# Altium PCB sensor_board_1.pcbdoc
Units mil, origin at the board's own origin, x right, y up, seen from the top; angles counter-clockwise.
Board outline 4127.56 x 3017.72 mil, 2 copper layers (Top Layer, Bottom Layer); 44 components, 32 nets, 169 pads, 48 vias.
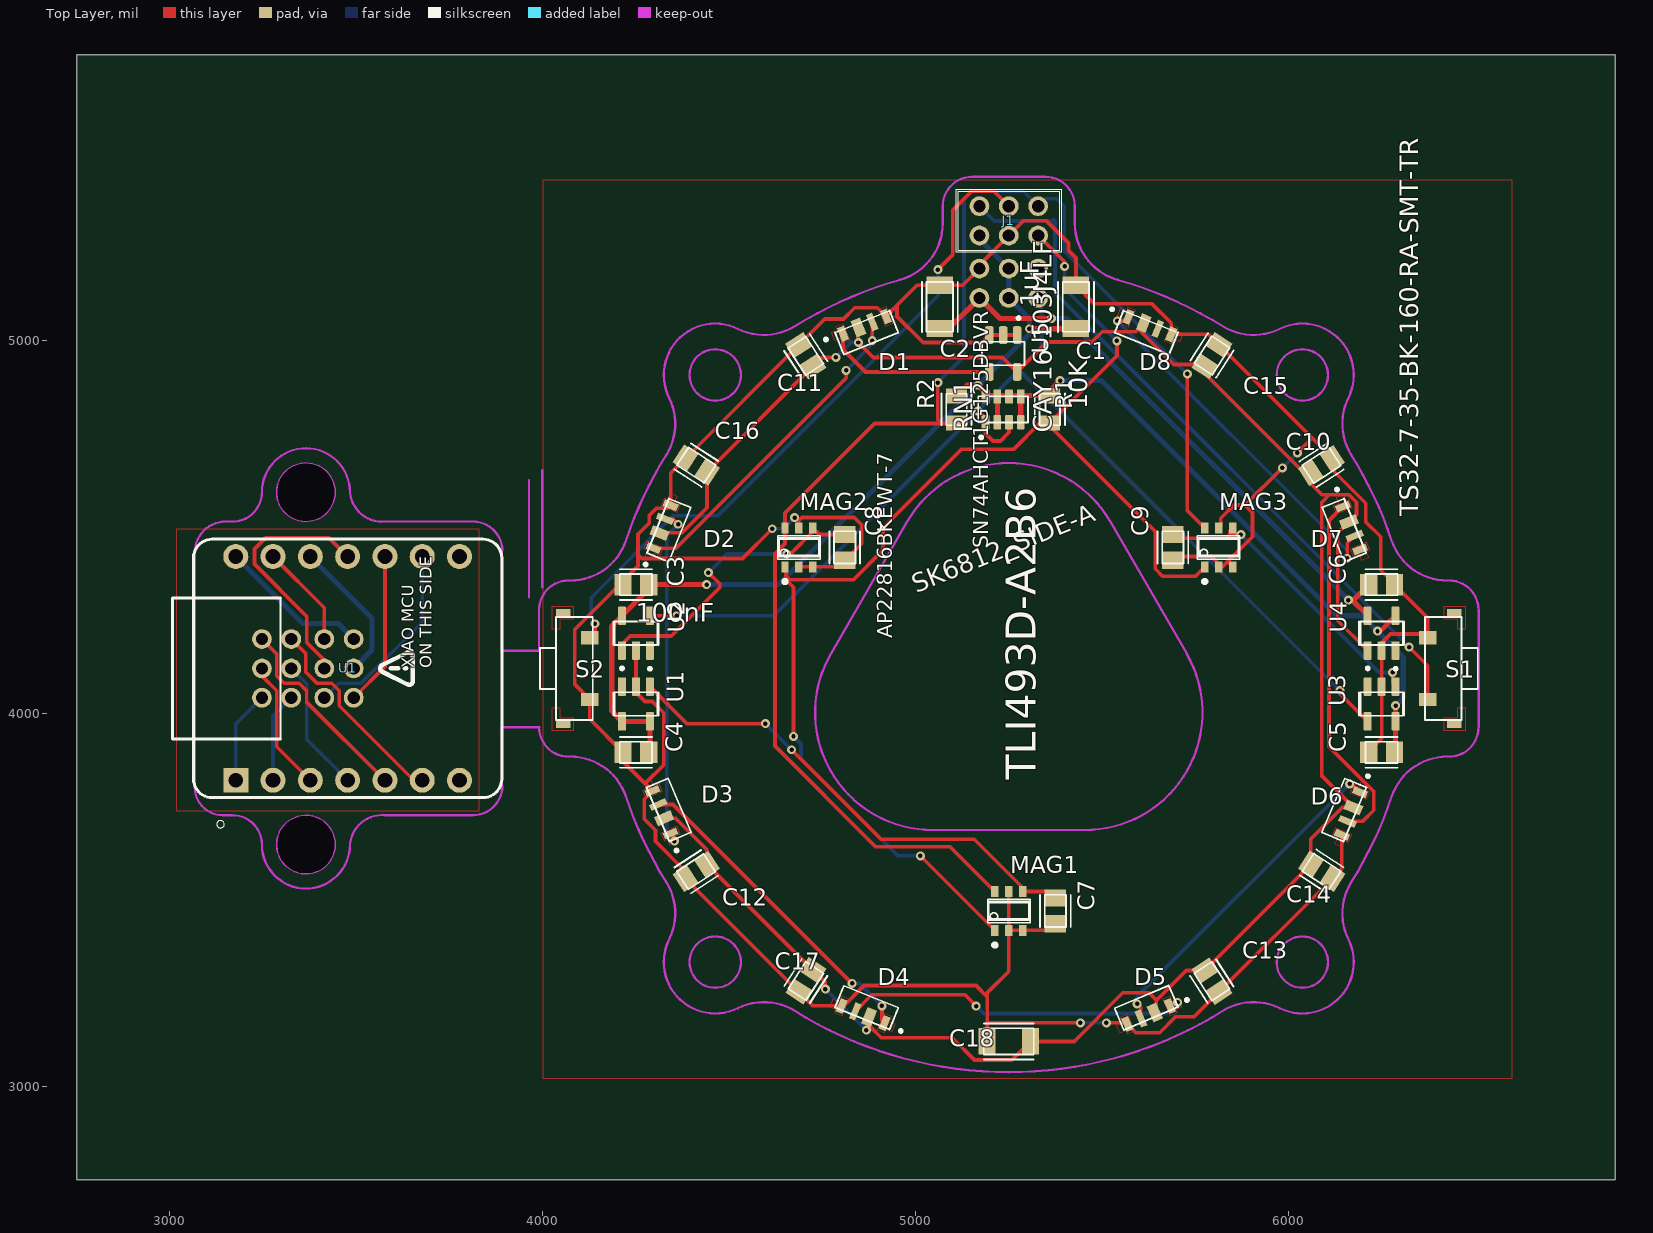
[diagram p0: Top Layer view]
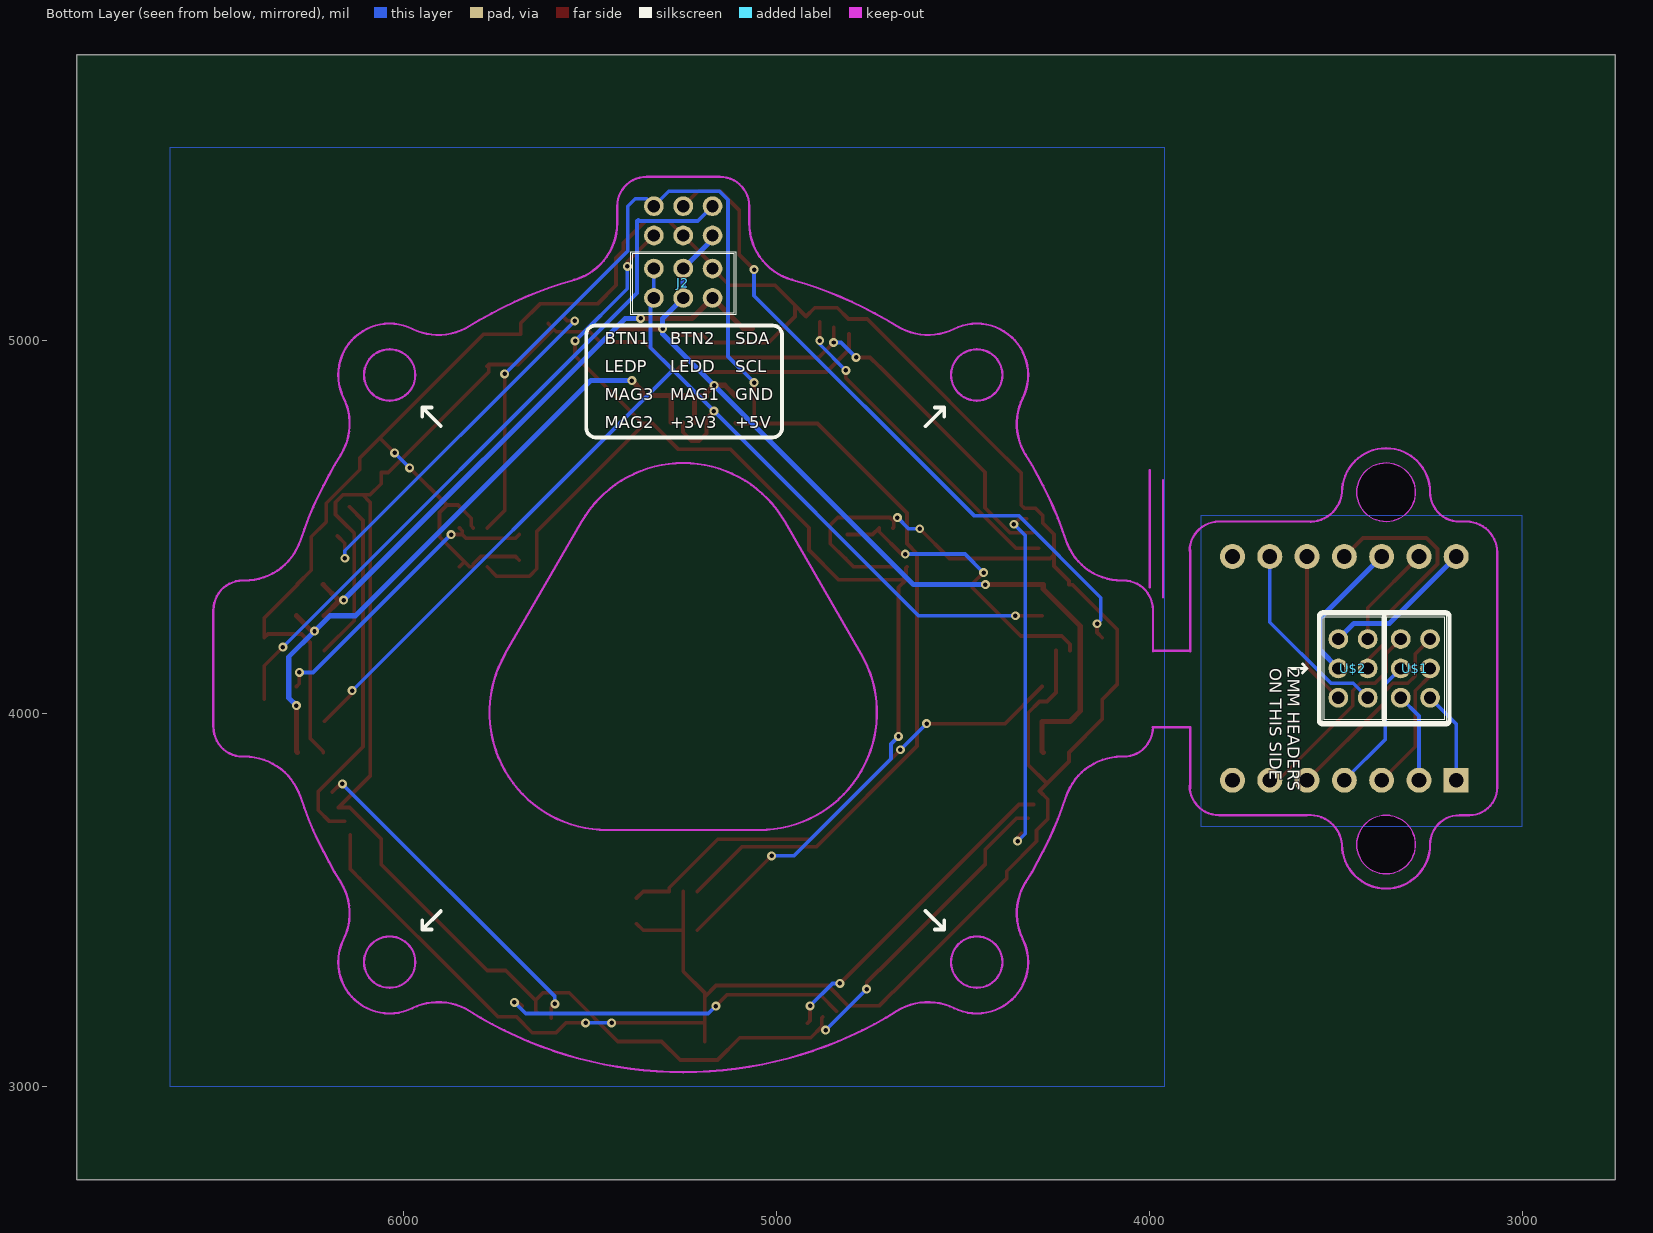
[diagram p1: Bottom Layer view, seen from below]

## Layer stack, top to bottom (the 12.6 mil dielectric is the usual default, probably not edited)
Top Layer: signal copper (thickness not stored)
Dielectric: dielectric 12.6, FR-4, Dk 4.8
Bottom Layer: signal copper (thickness not stored)

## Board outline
6877.56,2750 2750,2750 2750,5767.72 6877.56,5767.72
cut-out: 3444.05,3648.82 cw(c3365.31,3648.82) 3286.57,3648.82 cw(c3365.31,3648.82)
cut-out: 3444.05,4593.7 cw(c3365.31,4593.7) 3286.57,4593.7 cw(c3365.31,4593.7)

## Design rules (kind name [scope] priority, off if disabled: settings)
BoardOutlineClearance copperThickness1oz [All] p0: genericclearance=10 ignorepadtopadclearanceinfootprint=FALSE except(0: Arc-SplitContinuation Track-SplitContinuation SMDPad-SplitContinuation THPad-SplitContinuation Via-SplitContinuation Fill-SplitContinuation Poly-SplitContinuation Region-SplitContinuation Text-SplitContinuation; 6: SMDPad-CutoutEdge THPad-CutoutEdge Via-CutoutEdge Fill-CutoutEdge Region-CutoutEdge; 11.8: Track-OutlineEdge SMDPad-OutlineEdge THPad-OutlineEdge Via-OutlineEdge Fill-OutlineEdge Region-OutlineEdge Poly-OutlineEdge Text-OutlineEdge Track-CutoutEdge)
BoardOutlineClearance copperThickness2oz [All] p0: genericclearance=10 ignorepadtopadclearanceinfootprint=FALSE except(0: Arc-SplitContinuation Track-SplitContinuation SMDPad-SplitContinuation THPad-SplitContinuation Via-SplitContinuation Fill-SplitContinuation Poly-SplitContinuation Region-SplitContinuation Text-SplitContinuation; 6: SMDPad-CutoutEdge THPad-CutoutEdge Via-CutoutEdge Fill-CutoutEdge Region-CutoutEdge; 11.8: Track-OutlineEdge SMDPad-OutlineEdge THPad-OutlineEdge Via-OutlineEdge Fill-OutlineEdge Region-OutlineEdge Poly-OutlineEdge Text-OutlineEdge Track-CutoutEdge)
Clearance copperThickness1oz [(InNet('GND') OR InNet('N$1') OR InNet('N$2') OR InNet('N$4') OR InNet('N$5') OR InNet('N$6') OR InNet('G_5V') OR InNet('SCL') OR InNet('SDA') OR InNet('G_MAG1') OR InNet('G_MAG2') OR InNet('G_MAG3') OR InNet('BTN_1') OR InNet('BTN_2') OR InNet('LED_DIN') OR InNet('N$3') OR InNet('N$7') OR InNet('~EN_MAG2~') OR InNet('D3') OR InNet('D0') OR InNet('D1') OR InNet('D8') OR InNet('D9') OR InNet('D2') OR InNet('D10') OR InNet('SDA1') OR InNet('SCL1') OR InNet('GND1'))] p1: gap=7 ignorepadtopadclearanceinfootprint=FALSE except(4: Track-Track; 6: Track-SMDPad SMDPad-SMDPad Track-THPad SMDPad-THPad THPad-THPad Track-Via SMDPad-Via THPad-Via Via-Via Track-Fill SMDPad-Fill THPad-Fill Via-Fill Fill-Fill SMDPad-Region THPad-Region Via-Region Fill-Region Region-Region Track-Poly SMDPad-Poly THPad-Poly Via-Poly Fill-Poly Poly-Poly Track-Text SMDPad-Text THPad-Text Via-Text Fill-Text Region-Text Poly-Text Text-Text; 6.9: Track-Hole SMDPad-Hole THPad-Hole Via-Hole Fill-Hole Region-Hole Poly-Hole Text-Hole Sheet-Hole; 11.8: Track-Region Region-Poly Track-Sheet SMDPad-Sheet THPad-Sheet Via-Sheet Fill-Sheet Region-Sheet Poly-Sheet Text-Sheet)
Clearance copperThickness2oz [(InNet('5V') OR InNet('3V3') OR InNet('3V31') OR InNet('5V1'))] p1: gap=7 ignorepadtopadclearanceinfootprint=FALSE except(6: Track-SMDPad SMDPad-SMDPad Track-THPad SMDPad-THPad THPad-THPad Track-Via SMDPad-Via THPad-Via Via-Via Track-Fill SMDPad-Fill THPad-Fill Via-Fill Fill-Fill SMDPad-Region THPad-Region Via-Region Fill-Region Region-Region Track-Poly SMDPad-Poly THPad-Poly Via-Poly Fill-Poly Poly-Poly Track-Text SMDPad-Text THPad-Text Via-Text Fill-Text Region-Text Poly-Text Text-Text; 6.9: Track-Hole SMDPad-Hole THPad-Hole Via-Hole Fill-Hole Region-Hole Poly-Hole Text-Hole Sheet-Hole; 8: Track-Track; 11.8: Track-Region Region-Poly Track-Sheet SMDPad-Sheet THPad-Sheet Via-Sheet Fill-Sheet Region-Sheet Poly-Sheet Text-Sheet)
DiffPairsRouting differentialPair [All] p1: maxuncoupledlength=10 minlimit=5.9843 maxlimit=5.9843 mostfreqgap=5.9843 toplayer_minwidth=5 toplayer_prefwidth=10 toplayer_maxwidth=100 bottomlayer_minwidth=5 bottomlayer_prefwidth=10 bottomlayer_maxwidth=100
PasteMaskExpansion pasteMaskExpansion [All] p1: expansion=0
PlaneConnect innerPlane [All] p1: planeconnectstyle=Relief reliefexpansion=20 reliefentries=4 reliefconductorwidth=10 reliefairgap=10
PolygonConnect copperRegion [All] p1: connectstyle=Relief reliefentries=4 reliefconductorwidth=10 polygonreliefangle="90 Angle" airgapwidth=10
RoutingVias viaSize [All] p1: viastyle="Through Hole" holewidth=12.0078 minholewidth=11.811 maxholewidth=248.0314 width=24.0158 minwidth=19.685 maxwidth=393.7008
SolderMaskExpansion solderMaskExpansion [All] p1: useseparateexpansions=TRUE expansion=2.0079 expansionbottom=2.0079
Width copperThickness1oz [All] p1: maxlimit=100 minlimit=8 preferedwidth=10
Width copperThickness2oz [All] p1: maxlimit=100 minlimit=12 preferedwidth=14

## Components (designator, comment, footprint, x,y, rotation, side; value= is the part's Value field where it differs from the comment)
C1 "1uF" CAPC3216X135 5430.39,5090.87 r270 top
C2 "1uF" CAPC3216X135 5065.39,5090.87 r270 top
C3 "100nF" CAPC2012X110 4250.39,4345.87 r0 top
C4 "100nF" CAPC2012X110 4250.39,3895.87 r0 top
C5 "100nF" CAPC2012X110 6250.39,3895.87 r0 top
C6 "100nF" CAPC2012X110 6250.39,4345.87 r180 top
C7 "100nF" CAPC2012X110 5375.39,3470.87 r90 top
C8 "100nF" CAPC2012X110 4810.39,4445.87 r90 top
C9 "100nF" CAPC2012X110 5690.39,4445.87 r90 top
C10 "100nF" CAPC2012X110 6089.06,4665.51 r213 top
C11 "100nF" CAPC2012X110 4705.75,4959.54 r303 top
C12 "100nF" CAPC2012X110 4411.72,3576.23 r33 top
C13 "100nF" CAPC2012X110 5795.03,3282.2 r123 top
C14 "100nF" CAPC2012X110 6089.48,3577.11 r147 top
C15 "100nF" CAPC2012X110 5795.45,4960.42 r237 top
C16 "100nF" CAPC2012X110 4412.14,4666.39 r327 top
C17 "100nF" CAPC2012X110 4706.18,3283.08 r57 top
C18 "22uF" CAPC3216X135 5250.39,3120.87 r0 top
D1 "SK6812_SIDE-A" LED_SK6812_SIDE-A 4869.16,5022.12 r22 top
D2 "SK6812_SIDE-A" LED_SK6812_SIDE-A 4338.78,4491.75 r68 top
D3 "SK6812_SIDE-A" LED_SK6812_SIDE-A 4338.78,3741.69 r113 top
D4 "SK6812_SIDE-A" LED_SK6812_SIDE-A 4869.16,3211.32 r158 top
D5 "SK6812_SIDE-A" LED_SK6812_SIDE-A 5619.21,3211.32 r203 top
D6 "SK6812_SIDE-A" LED_SK6812_SIDE-A 6149.59,3741.69 r247 top
D7 "SK6812_SIDE-A" LED_SK6812_SIDE-A 6149.59,4491.75 r292 top
D8 "SK6812_SIDE-A" LED_SK6812_SIDE-A 5619.21,5022.12 r338 top
J1 "NPPN032AFCN-RCCONN3X2_NPPN032AFCN-RC_SUL" CONN3X2_NPPN032AFCN-RC_SUL 5250.39,5321.65 r0 top
J2 "NPPN032AFCN-RCCONN3X2_NPPN032AFCN-RC_SUL" CONN3X2_NPPN032AFCN-RC_SUL 5250.39,5154.33 r0 bottom
MAG1 "TLI493D-A2B6" SOP95P280X110-6N-V 5250.39,3470.87 r90 top
MAG2 "TLI493D-A2B6" SOP95P280X110-6N-V 4687.48,4445.87 r90 top
MAG3 "TLI493D-A2B6" SOP95P280X110-6N-V 5813.31,4445.87 r90 top
R1 "10K" RESC2012X65 5360.39,4815.87 r90 top
R2 "10K" RESC2012X65 5110.39,4815.87 r90 top
RN1 "CAY16-103J4LF" RESCAF80P320X160X60-8N 5235.39,4815.87 r90 top
S1 "TS32-7-35-BK-160-RA-SMT-TR" SW_TS32-7-35-BK-160-RA-SMT-TR 6425.39,4120.87 r90 top
S2 "TS32-7-35-BK-160-RA-SMT-TR" SW_TS32-7-35-BK-160-RA-SMT-TR 4075.39,4120.87 r270 top
U1 "AP22816BKEWT-7" SOT95P280X100-5N 4250.39,4025.87 r270 top
U1 "XIAO-THRUHOLE" XIAO-GENERIC-THRUHOLE-MODULE14P-2.54-21X17.8MM 3477.12,4121.26 r90 top
U2 "AP22816BKEWT-7" SOT95P280X100-5N 4250.39,4215.87 r90 top
U3 "AP22816BKEWT-7" SOT95P280X100-5N 6250.39,4025.87 r270 top
U4 "AP22816BKEWT-7" SOT95P280X100-5N 6250.39,4215.87 r90 top
U5 "SN74AHCT1G125DBVR" SOT95P280X145-5N 5235.39,4965.87 r270 top
U$1 "NRPN032PAEN-RC" CONN3X2_NRPN032PAEN-RC 3286.57,4121.26 r90 bottom
U$2 "NRPN032PAEN-RC" CONN3X2_NRPN032PAEN-RC 3453.9,4121.26 r90 bottom

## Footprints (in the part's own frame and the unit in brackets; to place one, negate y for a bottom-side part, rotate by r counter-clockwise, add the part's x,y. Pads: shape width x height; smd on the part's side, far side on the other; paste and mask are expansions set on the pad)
CAPC2012X110 [mil]
  rect 45.85x57.69 smd: 1(-34.46,0) 2(34.46,0)
  silkscreen extent -43,-41 43,41
CAPC3216X135 [mil]
  rect 45.85x71.47 smd: 1(-58.09,0) 2(58.09,0)
  silkscreen extent -67,-48 67,48
CONN3X2_NPPN032AFCN-RC_SUL [mil]
  round 53 hole 33: 1(78.74,39.37) 2(78.74,-39.37) 3(0,39.37) 4(0,-39.37) 5(-78.74,39.37) 6(-78.74,-39.37)
  silkscreen extent -142,-84 142,84
CONN3X2_NRPN032PAEN-RC [mil]
  round 53 hole 33: 1(78.74,39.37) 2(78.74,-39.37) 3(0,39.37) 4(0,-39.37) 5(-78.74,39.37) 6(-78.74,-39.37)
  silkscreen extent -142,-84 142,84
LED_SK6812_SIDE-A [mm]
  rect 0.5x1 smd: 1(-1.525,0.525) 4(1.625,0.525)
  rect 0.7x1.2 smd: 2(-0.4,0.525)
  rect 0.45x1.2 smd: 3(0.625,0.525)
  silkscreen extent -2.85,-0.8 2,0.8
RESC2012X65 [mil]
  rect 40.6x55.91 smd: 1(-36.2,0) 2(36.2,0)
  silkscreen extent -42,-40 42,40
RESCAF80P320X160X60-8N [mm]
  rrect25% 0.97x0.53 smd: 1(-0.875,1.2) 2(-0.875,0.4) 3(-0.875,-0.4) 4(-0.875,-1.2) 5(0.875,-1.2) 6(0.875,-0.4) 7(0.875,0.4) 8(0.875,1.2)
  silkscreen extent -2,-1.7 0.9,1.7
SOP95P280X110-6N-V [mm]
  rect 0.75x0.5 smd: 1(-1.325,0.95) 2(-1.325,0) 3(-1.325,-0.95) 4(1.325,-0.95) 5(1.325,0) 6(1.325,0.95)
  silkscreen extent -2.45,-1.45 0.8,1.45
SOT95P280X100-5N [mm]
  rrect25% 1.26x0.55 smd: 1(-1.185,0.95) 2(-1.185,0) 3(-1.185,-0.95) 4(1.185,-0.95) 5(1.185,0.95)
  silkscreen extent -2.5,-1.55 0.8,1.55
SOT95P280X145-5N [mm]
  rrect50% 1.21x0.59 smd: 1(-1.255,0.95) 2(-1.255,0) 3(-1.255,-0.95) 4(1.255,-0.95) 5(1.255,0.95)
  silkscreen extent -2.51,-1.45 0.8,1.45
SW_TS32-7-35-BK-160-RA-SMT-TR [mm]
  rect 0.9x1.2 smd: 1(-2.1,1.3) 2(2.1,1.3)
  rect 0.5x1 smd: SH1(-3.8,-0.5) SH2(3.8,-0.5)
  silkscreen extent -3.5,-2.1 3.5,1.5
XIAO-GENERIC-THRUHOLE-MODULE14P-2.54-21X17.8MM [mm]
  rect 1.7x1.7 hole 1: 1(-7.62,7.62)
  round 1.7 hole 1: 2(-7.62,5.08) 3(-7.62,2.54) 4(-7.62,0) 5(-7.62,-2.54) 6(-7.62,-5.08) 7(-7.62,-7.62) 8(7.62,-7.62) 9(7.62,-5.08) 10(7.62,-2.54) 11(7.62,0) 12(7.62,2.54) 13(7.62,5.08) 14(7.62,7.62)
  silkscreen extent -10.87,-10.5 8.8,11.92

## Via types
v1: diameter 24.02, hole 12.01, Top Layer to Bottom Layer, 48 vias

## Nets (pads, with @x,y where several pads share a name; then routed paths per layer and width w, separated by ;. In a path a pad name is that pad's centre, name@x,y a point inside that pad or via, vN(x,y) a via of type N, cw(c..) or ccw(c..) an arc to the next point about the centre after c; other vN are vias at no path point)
3V3: C1.2 C3.2 C4.2 C5.2 J1.6 J2.3 J2.4 R1.2 R2.2 RN1.2 RN1.4 RN1.5 RN1.6 RN1.7 RN1.8 U1.4@4212.99,3979.21 U1.5@4287.8,3979.21 U2.5 U3.5 U4.4 | length 4364.9
  Top Layer w13.78: C4.2 4287.8,3898.8 4287.8,3979.21 4212.99,3979.21 4185.43,4006.77 4185.43,4234.96 U2.5 4284.86,4334.39 C3.2 v1(4439.96,4345.87) ; R2.2 5139.04,4880.71 v1(5167.72,4880.71) RN1.8@5195.28,4853.15 ; RN1.8 5190.98,4853.15 RN1.8@5195.28,4853.15 ; RN1.2 RN1.7 RN1.7@5222.83,4853.15 ; RN1.6 RN1.6@5250.39,4853.15 ; RN1.4 RN1.5 RN1.5@5279.8,4853.15 ; v1(5305.51,5032.28) 5429.9,5032.28 C1.2 ; v1(5387.95,4893.41) 5360.39,4865.85 R1.2 5359.31,4853.15 RN1.5@5279.8,4853.15 ; v1(6239.31,4221.18) 6246.46,4221.18 U4.4 ; C5.2 6287.8,3898.8 U3.5 v1(6287.8,4021.64) ; RN1.8@5195.28,4853.15 RN1.7@5222.83,4853.15 ; RN1.7@5222.83,4853.15 RN1.6@5250.39,4853.15 ; RN1.6@5250.39,4853.15 RN1.5@5279.8,4853.15
  Bottom Layer w13.78: v1(4439.96,4345.87) 4632.87,4345.87 v1(5167.72,4880.71) 5305.51,5018.5 v1(5305.51,5032.28) 5305.51,5059.84 J2.3 J2.4 5171.65,5272.44 J1.6 ; v1(5387.95,4893.41) 5498.19,4893.41 6129.07,4262.52 6197.97,4262.52 v1(6239.31,4221.18) 6308.21,4152.28 6308.21,4042.05 v1(6287.8,4021.64)
3V31: U1.12 U$2.3 | length 388.9
  Bottom Layer w13.78: U1.12 3542.48,4255.91 3542.48,4170.47 U$2.3
5V: C2.2 C6.2 J2.5 U4.5 | length 1596.8
  Top Layer w13.78: C2.2 5089.47,5032.78 J2.5 5226.77,5059.84 v1(5364.57,5059.84) ; v1(6161.22,4304.53) v1@6170.98,4304.53 ; U4.5 v1@6170.98,4304.53 ; C6.2 6174.59,4304.53 v1@6170.98,4304.53
  Bottom Layer w13.78: v1(5364.57,5059.84) 5405.91,5059.84 v1(6161.22,4304.53)
5V1: U1.14 U$2.1 | length 407.8
  Bottom Layer w13.78: U1.14 3356.26,4242.13 3451.14,4242.13 U$2.1
BTN_1: J1.5 S1.1 | length 1919.1
  Top Layer w10: v1(6324.21,4178.19) 6374.21,4128.19 S1.1
  Bottom Layer w10: J1.5 5211.65,5321.02 5367.05,5321.02 5370.63,5324.61 5374.21,5321.02 5374.21,5128.19 v1(6324.21,4178.19)
BTN_2: J1.3 S2.1 | length 1816.7
  Top Layer w10: S2.1 4140.39,4217.36 v1(4140.39,4241.02) ; v1(5060.39,5191.02) 5100.39,5231.02 5100.39,5351.02 5150.39,5401.02 5210.39,5401.02 J1.3
  Bottom Layer w10: v1(4140.39,4241.02) 4130.39,4251.02 4130.39,4311.02 4350.39,4531.02 4470.39,4531.02 5060.39,5121.02 v1(5060.39,5191.02)
D0: U1.1@3177.12,3821.26 U$1.6 | length 250.3
  Bottom Layer w10: U1.1@3177.12,3821.26 3177.12,3972.44 U$1.6
D1: U1.2@3277.12,3821.26 U$1.5 | length 241.5
  Bottom Layer w10: U1.2@3277.12,3821.26 3277.12,3993.7 U$1.5
D2: U1.3@3377.12,3821.26 U$1.4 | length 353.8
  Top Layer w10: U$1.4 3247.2,4101.18 3287.12,4061.26 3287.12,3911.26 U1.3@3377.12,3821.26
D3: U1.4@3477.12,3821.26 U$1.3 | length 362.6
  Bottom Layer w10: U$1.3 3367.12,4080.08 3367.12,3931.26 U1.4@3477.12,3821.26
D8: U1.9 U$2.6 | length 522.7
  Bottom Layer w10: U$2.6 3453.27,4081.26 3513.27,4081.26 3677.12,4245.12 U1.9
D9: U1.10 U$2.5 | length 413.5
  Top Layer w10: U$2.5 3577.12,4126.38 U1.10
D10: U1.11 U$2.4 | length 680.8
  Top Layer w10: U$2.4 3414.53,4143.86 3367.12,4191.26 3367.12,4261.26 3227.12,4401.26 3227.12,4441.26 3257.12,4471.26 3427.12,4471.26 U1.11
G_5V: C10.2 C11.2 C12.2 C13.2 C14.2 C15.2 C16.2 C17.2 C18.2 D1.2 D2.2 D3.2 D4.2 D5.2 D6.2 D7.2 D8.2 U4.1 U5.5 | length 6401.2
  Top Layer w10: D2.2 4373.72,4484.89 4441.05,4552.22 C16.2 4724.06,4930.63 C11.2 4749.28,4955.39 v1(4786.81,4955.39) ; D3.2 4356.51,3719.12 4440.63,3635 C12.2 4723.64,3311.98 C17.2 4758.48,3278.45 v1(4758.48,3260.87) ; D1.2 v1(4846.81,4995.39) 4886.81,4955.39 5233.87,4955.39 U5.5 5352.8,4996.46 5472.8,4996.46 5500.79,5024.45 5590.79,5024.45 D8.2@5602.8,5036.46 ; v1(4868.48,3150.87) D4.2@4878.48,3160.87 ; D4.2 4878.48,3183.79 D4.2@4878.48,3160.87 ; D8.2 5612.36,5046.02 D8.2@5602.8,5036.46 ; D5.2 5646.26,3202.92 5646.26,3231.1 ; C15.2 C15.2@5771.74,4936.46 ; U4.1 6132.85,4249.35 6132.85,4484.09 D7.2 6182.85,4534.09 6182.85,4566.78 6162.85,4586.78 6110.16,4586.78 ; D4.2@4878.48,3160.87 4908.48,3130.87 5098.48,3130.87 5158.48,3070.87 5258.48,3070.87 C18.2 5426.03,3120.87 5556.26,3251.1 5626.26,3251.1 5646.26,3231.1 ; D8.2@5602.8,5036.46 5602.8,5026.46 5692.8,4936.46 C15.2@5771.74,4936.46 ; 5646.26,3231.1 5726.26,3311.1 C13.2 6060.58,3595.42 C14.2 6060.58,3663.92 6144.77,3748.11 D6.2 6090.16,3832.72 6090.16,4566.78 6110.16,4586.78 ; C15.2@5771.74,4936.46 5771.74,4916.46 6041.46,4646.73 C10.2 6060.16,4616.78 6090.16,4586.78 6110.16,4586.78
  Bottom Layer w10: v1(4758.48,3260.87) v1(4868.48,3150.87) ; v1(4786.81,4955.39) 4826.81,4995.39 v1(4846.81,4995.39)
G_MAG1: C7.2 MAG1.4 U1.1@4287.8,4072.52 | length 1328.4
  Top Layer w10: U1.1@4287.8,4072.52 4387.28,3973.03 v1(4597.8,3973.03) ; v1(4667.8,3903.03) 4907.8,3663.03 5157.8,3663.03 5287.8,3533.03 MAG1.4 5357.69,3523.03 C7.2
  Bottom Layer w10: v1(4597.8,3973.03) v1(4667.8,3903.03)
G_MAG2: C8.2 MAG2.4 U2.1 | length 822.6
  Top Layer w10: U2.1 4212.99,4186.15 4234.88,4208.03 4344.88,4208.03 4474.88,4338.03 4474.88,4348.03 v1(4444.88,4378.03) ; v1(4654.88,4428.03) 4664.88,4428.03 4724.88,4488.03 MAG2.4 4742.58,4480.33 C8.2
  Bottom Layer w10: v1(4444.88,4378.03) 4494.88,4428.03 v1(4654.88,4428.03)
G_MAG3: C9.2 MAG3.4 U3.1 | length 813.1
  Top Layer w10: C9.2 5700.39,4470.33 5833.01,4470.33 5843.01,4480.33 ; MAG3.4 5843.01,4490.33 5843.01,4480.33 ; v1(5873.01,4480.33) 5843.01,4480.33 ; v1(6279.98,4110.33) 6279.98,4080.33 U3.1
  Bottom Layer w10: v1(5873.01,4480.33) 6243.01,4110.33 v1(6279.98,4110.33)
GND: C1.1 C2.1 C3.1 C4.1 C5.1 C6.1 C7.1 C8.1 C9.1 C10.1 C11.1 C12.1 C13.1 C14.1 C15.1 C16.1 C17.1 C18.1 D1.4 D2.4 D3.4 D4.4 D5.4 D6.4 D8.4 J1.4 J2.6 MAG1.2 MAG1.3 MAG1.5 MAG2.2 MAG2.3 MAG2.5 MAG3.2 MAG3.3 MAG3.5 S1.2 S2.2 U1.2@4250.39,4072.52 U2.2 U3.2 U4.2 U5.1 U5.2 U5.3 | length 10085.4
  Top Layer w10: U2.2 4250.39,4072.52 4250.39,4056.87 4274.76,4032.5 4294.76,4032.5 4324.76,4002.5 4324.76,3862.5 4274.76,3812.5 ; v1(4615.93,4495.87) 4535.93,4415.87 4265.93,4415.87 4255.93,4425.87 ; v1(4675.93,4525.87) 4685.93,4515.87 ; MAG2.2 MAG2.3 4793.76,4393.7 C8.1@4815.93,4415.87 ; MAG2.5 4685.93,4499.58 4685.93,4515.87 ; C8.1 4814.86,4415.87 C8.1@4815.93,4415.87 ; C18.1 5192.31,3170.61 ; MAG1.5 MAG1.2 ; U5.1 U5.2 U5.3 5177.97,4995.25 5020.73,4995.25 4950.73,5065.25 4950.73,5095.25 ; C7.1 5357.69,3418.7 MAG1.3 MAG1.2 ; v1(5442.31,3170.61) 5192.31,3170.61 ; v1(5512.31,3170.61) 5565.08,3170.61 D5.4 5591.39,3144.3 5655.41,3144.3 5698.4,3187.29 5747.8,3187.29 C13.1 C14.1@6113.8,3553.29 ; C9.1 5700.39,4421.4 5793.31,4421.4 5813.31,4401.4 MAG3.2 5823.31,4393.7 5834.22,4404.61 ; MAG3.5 5818.87,4503.59 5818.87,4523.97 5854.22,4559.32 5884.22,4559.32 ; MAG3.3 5839.8,4404.61 5834.22,4404.61 ; v1(5984.22,4659.32) 5884.22,4559.32 ; v1(6024.22,4699.32) 6064.22,4739.32 ; C14.1 C14.1@6113.8,3553.29 ; D6.4 6143.62,3583.1 C14.1@6113.8,3553.29 ; C5.1 6215.93,3898.06 6250.39,3932.52 U3.2 U4.2 6250.39,4189.72 6274.21,4213.54 6364.21,4213.54 S1.2 6374.21,4256.51 C6.1 6284.86,4347.39 6247.97,4384.28 6247.97,4474.28 6207.97,4514.28 6207.97,4564.28 6117.97,4654.28 C10.1 6117.97,4685.58 6064.22,4739.32 ; 4255.93,4425.87 4255.93,4395.87 4215.93,4355.87 C3.1 4205.93,4345.87 4086.57,4226.51 4086.57,4078.19 S2.2 4126.57,3985.22 C4.1 4215.93,3871.34 4274.76,3812.5 ; 4255.93,4425.87 4255.93,4481.15 4285.93,4511.15 4285.93,4531.15 4305.93,4551.15 4335.93,4551.15 D2.4 4343.59,4645.51 C16.1 4383.7,4685.16 C11.1 4756.98,5058.44 4806.98,5058.44 4836.98,5088.44 4897.54,5088.44 D1.4 4950.73,5095.25 ; 4274.76,3812.5 D3.4 4272.82,3770.56 4272.82,3717.46 4302.82,3687.46 4302.82,3657.46 4382.82,3577.46 C12.1 4686.1,3254.18 C17.1 4725.46,3216.12 D4.4 4807.81,3216.12 4862.31,3270.61 5162.31,3270.61 5192.31,3240.61 ; 4685.93,4515.87 4695.93,4525.87 4835.93,4525.87 4855.93,4505.87 4855.93,4455.87 C8.1@4815.93,4415.87 ; 4950.73,5095.25 5004.43,5148.95 C2.1 5126.91,5148.95 J2.6 5171.65,5203.54 J1.4 5290.39,5322.28 5350.39,5322.28 5410.39,5262.28 5410.39,5242.28 5430.39,5222.28 C1.1 5480.39,5098.95 5634.64,5098.95 5686.27,5047.32 D8.4 5786.23,5017.32 C15.1 6064.22,4739.32 ; 5192.31,3170.61 5192.31,3240.61 ; 5192.31,3240.61 5192.31,3250.61 5250.39,3308.7 MAG1.2 ; 5834.22,4404.61 5904.22,4474.61 5904.22,4539.32 5884.22,4559.32
  Bottom Layer w10: v1(4615.93,4495.87) 4645.93,4495.87 v1(4675.93,4525.87) ; v1(5442.31,3170.61) v1(5512.31,3170.61) ; v1(5984.22,4659.32) v1(6024.22,4699.32)
GND1: U1.13 U$2.2 | length 278.2
  Top Layer w10: U1.13 3414.53,4283.86 U$2.2
LED_DIN: D1.1 U5.4 | length 459.4
  Top Layer w10: D1.1 4805.75,4976.46 4865.75,4916.46 U5.4
N$1: D1.3 D2.1 | length 885.3
  Top Layer w10: D2.1 4357.55,4443.82 4814.23,4900.5 v1(4814.23,4920.5) ; v1(4884.23,5000.5) D1.3
  Bottom Layer w10: v1(4814.23,4920.5) 4884.23,4990.5 v1(4884.23,5000.5)
N$2: D2.3 D3.1 | length 935.6
  Top Layer w10: D2.3 4348.84,4522.3 v1(4363.22,4507.92) ; D3.1 4353.22,3668.35 v1(4353.22,3657.92)
  Bottom Layer w10: v1(4353.22,3657.92) 4333.22,3677.92 4333.22,4477.92 v1(4363.22,4507.92)
N$3: D6.3 D7.1 | length 961.8
  Top Layer w10: D7.1 6109,4517.9 6109,3910.96 6229,3790.96 6229,3740.96 6199,3710.96 D6.3
N$4: D3.3 D4.1 | length 873.2
  Top Layer w10: D3.3 4350.14,3756.26 v1(4830.14,3276.26) ; v1(4910.14,3216.26) 4910.14,3176.6 D4.1
  Bottom Layer w10: v1(4830.14,3276.26) 4850.14,3276.26 v1(4910.14,3216.26)
N$5: D4.3 D5.1 | length 940.5
  Top Layer w10: D4.3 4882.98,3245.75 5132.98,3245.75 v1(5162.98,3215.75) ; D5.1 5692.56,3225.75 v1(5702.98,3225.75)
  Bottom Layer w10: v1(5162.98,3215.75) 5182.98,3195.75 5672.98,3195.75 v1(5702.98,3225.75)
N$6: D5.3 D6.1 | length 905.8
  Top Layer w10: v1(5594.64,3221.45) 5604.64,3211.45 D5.3 ; v1(6164.64,3811.45) 6169.51,3811.45 D6.1
  Bottom Layer w10: v1(5594.64,3221.45) 5594.64,3241.45 v1(6164.64,3811.45)
N$7: D7.3 D8.1 | length 994.7
  Top Layer w10: v1(5541.29,5053.36) 5560.87,5053.36 D8.1 ; v1(6157.97,4416.67) 6157.97,4456.67 D7.3
  Bottom Layer w10: v1(5541.29,5053.36) 6157.97,4436.67 v1(6157.97,4416.67)
SCL: J1.2 MAG1.1 MAG2.1 MAG3.1 R1.1 | length 3490.4
  Top Layer w10: MAG2.1 4652.99,4390.78 4652.99,4368.7 ; v1(4672.99,3938.7) 4672.99,4338.7 4652.99,4358.7 4652.99,4368.7 ; v1(5012.99,3618.7) MAG1.1 ; J1.2 5400.39,5211.02 v1(5400.39,5199.67) ; v1(5540.39,4999.67) 5540.39,4959.67 R1.1 R1.1@5352.99,4778.7 ; MAG3.1 5750.91,4368.7 5662.99,4368.7 5642.99,4388.7 5642.99,4488.7 R1.1@5352.99,4778.7 ; 4652.99,4368.7 4662.99,4358.7 4832.99,4358.7 4912.99,4438.7 4912.99,4498.7 5122.99,4708.7 5262.99,4708.7 5332.99,4778.7 R1.1@5352.99,4778.7
  Bottom Layer w10: v1(4672.99,3938.7) 4692.99,3918.7 4692.99,3878.7 4952.99,3618.7 v1(5012.99,3618.7) ; v1(5400.39,5199.67) 5400.39,5139.67 v1(5540.39,4999.67)
SCL1: U1.6 U$1.1 | length 560.8
  Top Layer w10: U$1.1 3364.68,4161.26 3364.68,4111.26 3394.68,4081.26 3434.68,4081.26 3454.68,4061.26 3454.68,4021.26 3654.68,3821.26 U1.6
SDA: J1.1 MAG1.6 MAG2.6 MAG3.6 R2.1 | length 3912
  Top Layer w10: v1(5060.07,4888.03) 5060.07,4788.03 5070.07,4778.03 ; R2.1 5108.76,4778.03 5070.07,4778.03 ; MAG1.6 5092.99,3643.03 4892.99,3643.03 4623.07,3912.96 4623.07,4428.94 4650.07,4455.95 MAG2.6 4650.07,4538.03 4890.07,4778.03 5070.07,4778.03 ; v1(5729.13,4911.02) 5729.13,4544.81 MAG3.6
  Bottom Layer w10: v1(5060.07,4888.03) 5130.07,4958.03 5130.07,5378.03 5153.07,5401.02 5289.13,5401.02 J1.1 5349.13,5381.02 5379.13,5381.02 5399.13,5361.02 5399.13,5241.02 v1(5729.13,4911.02)
SDA1: U1.5@3577.12,3821.26 U$1.2 | length 538.8
  Top Layer w10: U$1.2 3287.12,4160.08 3287.12,4101.26 3307.12,4081.26 3347.12,4081.26 3367.12,4061.26 3367.12,4031.26 U1.5@3577.12,3821.26
~EN_MAG2~: J2.1 J2.2 RN1.1 RN1.3 U2.4 U3.4 | length 3069.7
  Top Layer w10: U2.4 v1(4359.25,4262.52) ; v1(5168.15,4811.42) 5188.15,4791.42 RN1.1 5188.15,4751.42 5208.15,4731.42 5228.15,4731.42 5251.14,4754.41 RN1.3 ; v1(6138.15,4061.42) 6138.15,4054.06 U3.4
  Bottom Layer w10: v1(4359.25,4262.52) 4619.25,4262.52 v1(5168.15,4811.42) 5278.15,4921.42 ; J2.2 J2.1 5338.15,5105.94 5338.15,4981.42 5278.15,4921.42 ; v1(6138.15,4061.42) 5278.15,4921.42
pads on no net: D7.4 D8.3 S1.SH1 S1.SH2 S2.SH1 S2.SH2 U1.3@4212.99,4072.52 U1.7 U1.8 U2.3 U3.3 U4.3

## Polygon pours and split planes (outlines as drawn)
GND on Bottom Layer (solid, remove dead copper, pour order 4): 3959.45,5517.72 6627.56,5517.72 6627.56,3000 3959.45,3000
GND1 on Bottom Layer (solid, remove dead copper, pour order 6): 3000,4530.71 3861.81,4530.71 3861.81,3697.64 3000,3697.64
GND on Top Layer (solid, remove dead copper, pour order 8): 4002.36,5432.28 6598.82,5432.28 6598.82,3021.26 4002.36,3021.26
GND1 on Top Layer (solid, remove dead copper, pour order 10): 3018.9,4495.28 3828.74,4495.28 3828.74,3737.8 3018.9,3737.8
no net on Top Layer (solid, remove dead copper, pour order 2): 4950.15,5068.64 4942.04,5088.72 4925.72,5082.13 4925.57,5082.19 4921.92,5091.21 4901.85,5083.1 4919.54,5039.29 4939.62,5047.4 4933.76,5061.9 4933.83,5062.05
no net on Top Layer (solid, remove dead copper, pour order 2): 4798.55,5007.39 4798.7,5007.33 4804.56,4992.84 4824.64,5000.95 4806.94,5044.75 4786.86,5036.64 4790.5,5027.62 4790.44,5027.47 4774.12,5020.88 4782.23,5000.8
no net on Top Layer (solid, remove dead copper, pour order 2): 6476.57,4014.57 6452.95,4014.57 6452.95,3987.12 6452.84,3987.01 6417.52,3987.01 6417.52,3955.51 6476.57,3955.51
no net on Top Layer (solid, remove dead copper, pour order 2): 6417.52,4254.72 6452.84,4254.72 6452.95,4254.61 6452.95,4227.17 6476.57,4227.17 6476.57,4286.22 6417.52,4286.22
no net on Top Layer (solid, remove dead copper, pour order 2): 4361.58,4582.32 4341.5,4590.43 4334.91,4574.11 4334.76,4574.05 4325.74,4577.69 4317.63,4557.62 4361.43,4539.92 4369.54,4560 4355.05,4565.85 4354.99,4566
no net on Top Layer (solid, remove dead copper, pour order 2): 4300.33,4430.73 4300.48,4430.79 4314.97,4424.93 4323.09,4445.01 4279.28,4462.71 4271.17,4442.63 4280.19,4438.99 4280.25,4438.84 4273.66,4422.52 4293.74,4414.41
no net on Top Layer (solid, remove dead copper, pour order 2): 4290.86,3821.86 4270.92,3813.39 4277.8,3797.19 4277.74,3797.04 4268.79,3793.24 4277.25,3773.31 4320.73,3791.77 4312.27,3811.7 4297.88,3805.59 4297.73,3805.65
no net on Top Layer (solid, remove dead copper, pour order 2): 4354.74,3671.35 4354.8,3671.5 4369.19,3677.61 4360.73,3697.54 4317.24,3679.08 4325.7,3659.15 4334.66,3662.95 4334.81,3662.89 4341.69,3646.69 4361.62,3655.15
no net on Top Layer (solid, remove dead copper, pour order 2): 4778.58,3234.11 4770.47,3214.03 4786.79,3207.44 4786.85,3207.29 4783.21,3198.27 4803.29,3190.16 4820.98,3233.96 4800.91,3242.08 4795.05,3227.58 4794.9,3227.52
no net on Top Layer (solid, remove dead copper, pour order 2): 4930.18,3172.86 4930.11,3173.01 4935.97,3187.51 4915.89,3195.62 4898.2,3151.81 4918.27,3143.7 4921.92,3152.72 4922.07,3152.79 4938.39,3146.19 4946.5,3166.27
no net on Top Layer (solid, remove dead copper, pour order 2): 5539.05,3163.39 5547.51,3143.46 5563.71,3150.33 5563.86,3150.27 5567.66,3141.32 5587.6,3149.78 5569.14,3193.27 5549.2,3184.81 5555.31,3170.42 5555.25,3170.26
no net on Top Layer (solid, remove dead copper, pour order 2): 5689.55,3227.27 5689.4,3227.33 5683.29,3241.72 5663.36,3233.26 5681.82,3189.77 5701.75,3198.24 5697.95,3207.19 5698.01,3207.34 5714.22,3214.22 5705.75,3234.15
no net on Top Layer (solid, remove dead copper, pour order 2): 6125.22,3651.53 6145.15,3643.07 6152.03,3659.27 6152.18,3659.33 6161.13,3655.53 6169.59,3675.46 6126.1,3693.92 6117.64,3673.99 6132.03,3667.88 6132.09,3667.73
no net on Top Layer (solid, remove dead copper, pour order 2): 6189.1,3802.03 6188.95,3801.97 6174.56,3808.08 6166.1,3788.14 6209.59,3769.68 6218.05,3789.62 6209.09,3793.42 6209.03,3793.57 6215.91,3809.77 6195.98,3818.23
no net on Top Layer (solid, remove dead copper, pour order 2): 6196.11,4410.76 6216.19,4418.87 6209.59,4435.19 6209.66,4435.34 6218.68,4438.98 6210.56,4459.06 6166.76,4441.36 6174.87,4421.28 6189.37,4427.14 6189.52,4427.08
no net on Top Layer (solid, remove dead copper, pour order 2): 6134.86,4562.35 6134.8,4562.2 6120.3,4556.35 6128.42,4536.27 6172.22,4553.97 6164.11,4574.04 6155.09,4570.4 6154.94,4570.46 6148.35,4586.78 6128.27,4578.67
no net on Top Layer (solid, remove dead copper, pour order 2): 5709.79,4999.33 5717.9,5019.4 5701.58,5026 5701.52,5026.15 5705.16,5035.17 5685.09,5043.28 5667.39,4999.47 5687.46,4991.36 5693.32,5005.86 5693.47,5005.92
no net on Top Layer (solid, remove dead copper, pour order 2): 5558.19,5060.57 5558.26,5060.42 5552.4,5045.93 5572.48,5037.82 5590.18,5081.62 5570.1,5089.73 5566.46,5080.72 5566.31,5080.65 5549.99,5087.24 5541.88,5067.17
no net on Top Layer (solid, remove dead copper, pour order 2): 4024.21,4227.17 4047.83,4227.17 4047.83,4254.61 4047.95,4254.72 4083.27,4254.72 4083.27,4286.22 4024.21,4286.22
no net on Top Layer (solid, remove dead copper, pour order 2): 4083.27,3987.01 4047.95,3987.01 4047.83,3987.12 4047.83,4014.57 4024.21,4014.57 4024.21,3955.51 4083.27,3955.51

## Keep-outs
Board Outline Layer:
  circle w6: c6037.8,4908.27 r68.9
  circle w6: c4462.99,4908.27 r68.9
  circle w6: c4462.99,3333.46 r68.9
  circle w6: c6037.8,3333.46 r68.9
  circle w1: c3365.31,3648.82 r78.74
  region: 3444.05,3648.82 cw(c3365.31,3648.82) 3286.57,3648.82 cw(c3365.31,3648.82)
  circle w1: c3365.31,4593.7 r78.74
  region: 3444.05,4593.7 cw(c3365.31,4593.7) 3286.57,4593.7 cw(c3365.31,4593.7)
  lines w6: 3889.74,4168.9 3990.58,4168.9 ; 3890.51,3799.26 3890.51,3962.32 ; 3890.49,3963.39 3991.34,3963.39 ; 3890.51,4166.75 3890.51,4278.65 ; 3890.51,4279.22 3890.51,4438.99 ; 3892.12,3806.3 cw(c3813.38,3806.3) 3813.38,3727.56 3577.16,3727.56 ccw(c3569.66,3641.32) 3483.42,3648.82 cw(c3365.31,3648.82) 3247.2,3648.82 ccw(c3168.46,3648.82) 3168.46,3727.56 3142.09,3727.56 cw(c3142.09,3802.52) 3067.12,3802.52 3067.12,4432.44 cw(c3149.64,4432.44) 3149.64,4514.96 3168.46,4514.96 ccw(c3168.46,4593.7) 3247.2,4593.7 cw(c3365.31,4593.7) 3483.42,4593.7 ccw(c3569.66,4601.2) 3577.16,4514.96 3813.38,4514.96 cw(c3813.38,4436.22) 3892.12,4436.22 ; 3963.78,4311.42 3963.78,4626.38 ; 3990.55,3963.39 ccw(c4069.29,3963.39) 4069.29,3884.65 4074.39,3884.65 cw(c4074.39,3727.17) 4223.72,3777.16 ccw(c5250.39,4120.87) 4331.89,3547.68 cw(c4198.29,3464.31) 4339.46,3394.53 ccw(c4462.99,3333.46) 4524.05,3209.94 cw(c4593.84,3068.76) 4677.21,3202.36 ccw(c5250.39,4120.87) 5823.58,3202.36 cw(c5906.95,3068.76) 5976.73,3209.94 ccw(c6037.8,3333.46) 6161.32,3394.53 cw(c6302.5,3464.31) 6168.9,3547.68 ccw(c5250.39,4120.87) 6277.07,3777.16 cw(c6426.4,3727.17) 6426.4,3884.65 6431.5,3884.65 ccw(c6431.5,3963.39) 6510.24,3963.39 ; 3990.55,4278.35 cw(c4069.29,4278.35) 4069.29,4357.09 4074.39,4357.09 ccw(c4074.39,4514.57) 4223.72,4464.57 cw(c5250.39,4120.87) 4331.89,4694.05 ccw(c4198.29,4777.42) 4339.46,4847.21 cw(c4462.99,4908.27) 4524.05,5031.8 ccw(c4593.84,5172.97) 4677.21,5039.37 cw(c5250.39,4120.87) 4958.24,5163.38 ccw(c4915.75,5315.02) 5073.23,5315.02 5073.23,5361.02 cw(c5151.97,5361.02) 5151.97,5439.76 5348.82,5439.76 cw(c5348.82,5361.02) 5427.56,5361.02 5427.56,5315.02 ccw(c5585.04,5315.02) 5542.54,5163.38 cw(c5250.39,4120.87) 5823.58,5039.37 ccw(c5906.95,5172.97) 5976.73,5031.8 cw(c6037.8,4908.27) 6161.32,4847.21 ccw(c6302.5,4777.42) 6168.9,4694.05 cw(c5250.39,4120.87) 6277.07,4464.57 ccw(c6426.4,4514.57) 6426.4,4357.09 6431.5,4357.09 cw(c6431.5,4278.35) 6510.24,4278.35 ; 3990.58,4166.45 3990.58,4278.35 ; 3998.82,4338.19 3998.82,4653.15 ; 6510.63,3964.17 6510.63,4279.13 ; 4773.06,4160.24 ccw(c5045.82,4002.76) 5045.82,3687.8 5454.97,3687.8 ccw(c5454.97,4002.76) 5727.73,4160.24 5523.16,4514.57 ccw(c5250.39,4357.09) 4977.63,4514.57 4773.06,4160.24

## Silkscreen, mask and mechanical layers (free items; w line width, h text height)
Top Silkscreen Layer:
  lines w12: 3593.12,4121.26 3613.12,4121.26 ; 3630.64,4121.26 3634.12,4121.26 ; 3570.01,4112.32 3637.65,4078.5 ccw(c3642.12,4087.44) 3652.12,4087.44 3652.12,4155.08 ccw(c3642.12,4155.08) 3637.65,4164.02 3570.01,4130.2 ccw(c3574.49,4121.26) 3570.01,4112.32
  text "XIAO MCU / ON THIS SIDE" at 3702.12,4121.26 h32 r90
Bottom Silkscreen Layer:
  lines w8: 3589.1,4133.46 3577.12,4121.26 ; 3589.32,4109.28 3577.12,4121.26 ; 3627.12,4121.26 3577.12,4121.26
  lines w10: 4550.39,3445.87 4550.39,3420.87 ; 4550.39,4795.87 4550.39,4820.87 ; 4575.39,3420.87 4550.39,3420.87 ; 4575.39,4820.87 4550.39,4820.87 ; 4600.39,3470.87 4550.39,3420.87 ; 4600.39,4770.87 4550.39,4820.87 ; 5900.39,3470.87 5950.39,3420.87 ; 5900.39,4770.87 5950.39,4820.87 ; 5925.39,3420.87 5950.39,3420.87 ; 5925.39,4820.87 5950.39,4820.87 ; 5950.39,3445.87 5950.39,3420.87 ; 5950.39,4795.87 5950.39,4820.87 ; 4985.39,4765.87 ccw(c5010.39,4765.87) 5010.39,4740.87 5485.39,4740.87 ccw(c5485.39,4765.87) 5510.39,4765.87 5510.39,5015.87 ccw(c5485.39,5015.87) 5485.39,5040.87 5010.39,5040.87 ccw(c5010.39,5015.87) 4985.39,5015.87 4985.39,4765.87
  lines w12: 3370.12,3971.26 3535.12,3971.26 ccw(c3535.12,3981.26) 3545.12,3981.26 3545.12,4261.26 ccw(c3535.12,4261.26) 3535.12,4271.26 3370.12,4271.26 ; 3370.12,3971.26 3205.12,3971.26 cw(c3205.12,3981.26) 3195.12,3981.26 3195.12,4261.26 cw(c3205.12,4261.26) 3205.12,4271.26 3370.12,4271.26 ; 3370.12,3971.26 3370.12,4271.26
  text "SDA" at 5110.39,4990.87 h32
  text "BTN2" at 5285.39,4990.87 h32
  text "BTN1" at 5460.39,4990.87 h32
  text "SCL" at 5110.39,4915.87 h32
  text "LEDD" at 5285.39,4915.87 h32
  text "LEDP" at 5460.39,4915.87 h32
  text "GND" at 5110.39,4840.87 h32
  text "MAG1" at 5285.39,4840.87 h32
  text "MAG3" at 5460.39,4840.87 h32
  text "+5V" at 5110.39,4765.87 h32
  text "+3V3" at 5285.39,4765.87 h32
  text "MAG2" at 5460.39,4765.87 h32
  text "2MM HEADERS / ON THIS SIDE" at 3677.12,4121.26 h32 r90
Mechanical Layer:
  circle w1: c3365.31,3648.82 r78.74
  circle w1: c3365.31,4593.7 r78.74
